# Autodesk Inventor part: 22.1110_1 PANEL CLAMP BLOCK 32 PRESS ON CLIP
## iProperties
Created: 2007-04
Part Number: 22.1110_1 PANEL CLAMP BLOCK 32 PRESS ON CLIP
Material: ABS Plastic
Document SubType Name: Modeling
Designer: Andy Moles
Density: 1.06 g/cm^3
Author: Andy Moles
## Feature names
1. Base1
